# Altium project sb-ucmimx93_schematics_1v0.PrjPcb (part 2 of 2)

## Sheet 10 Console, RS232, SD, .SchDoc
size 420 x 297 mm; DocumentNumber: 10; SheetNumber: 10; SheetTotal: 12
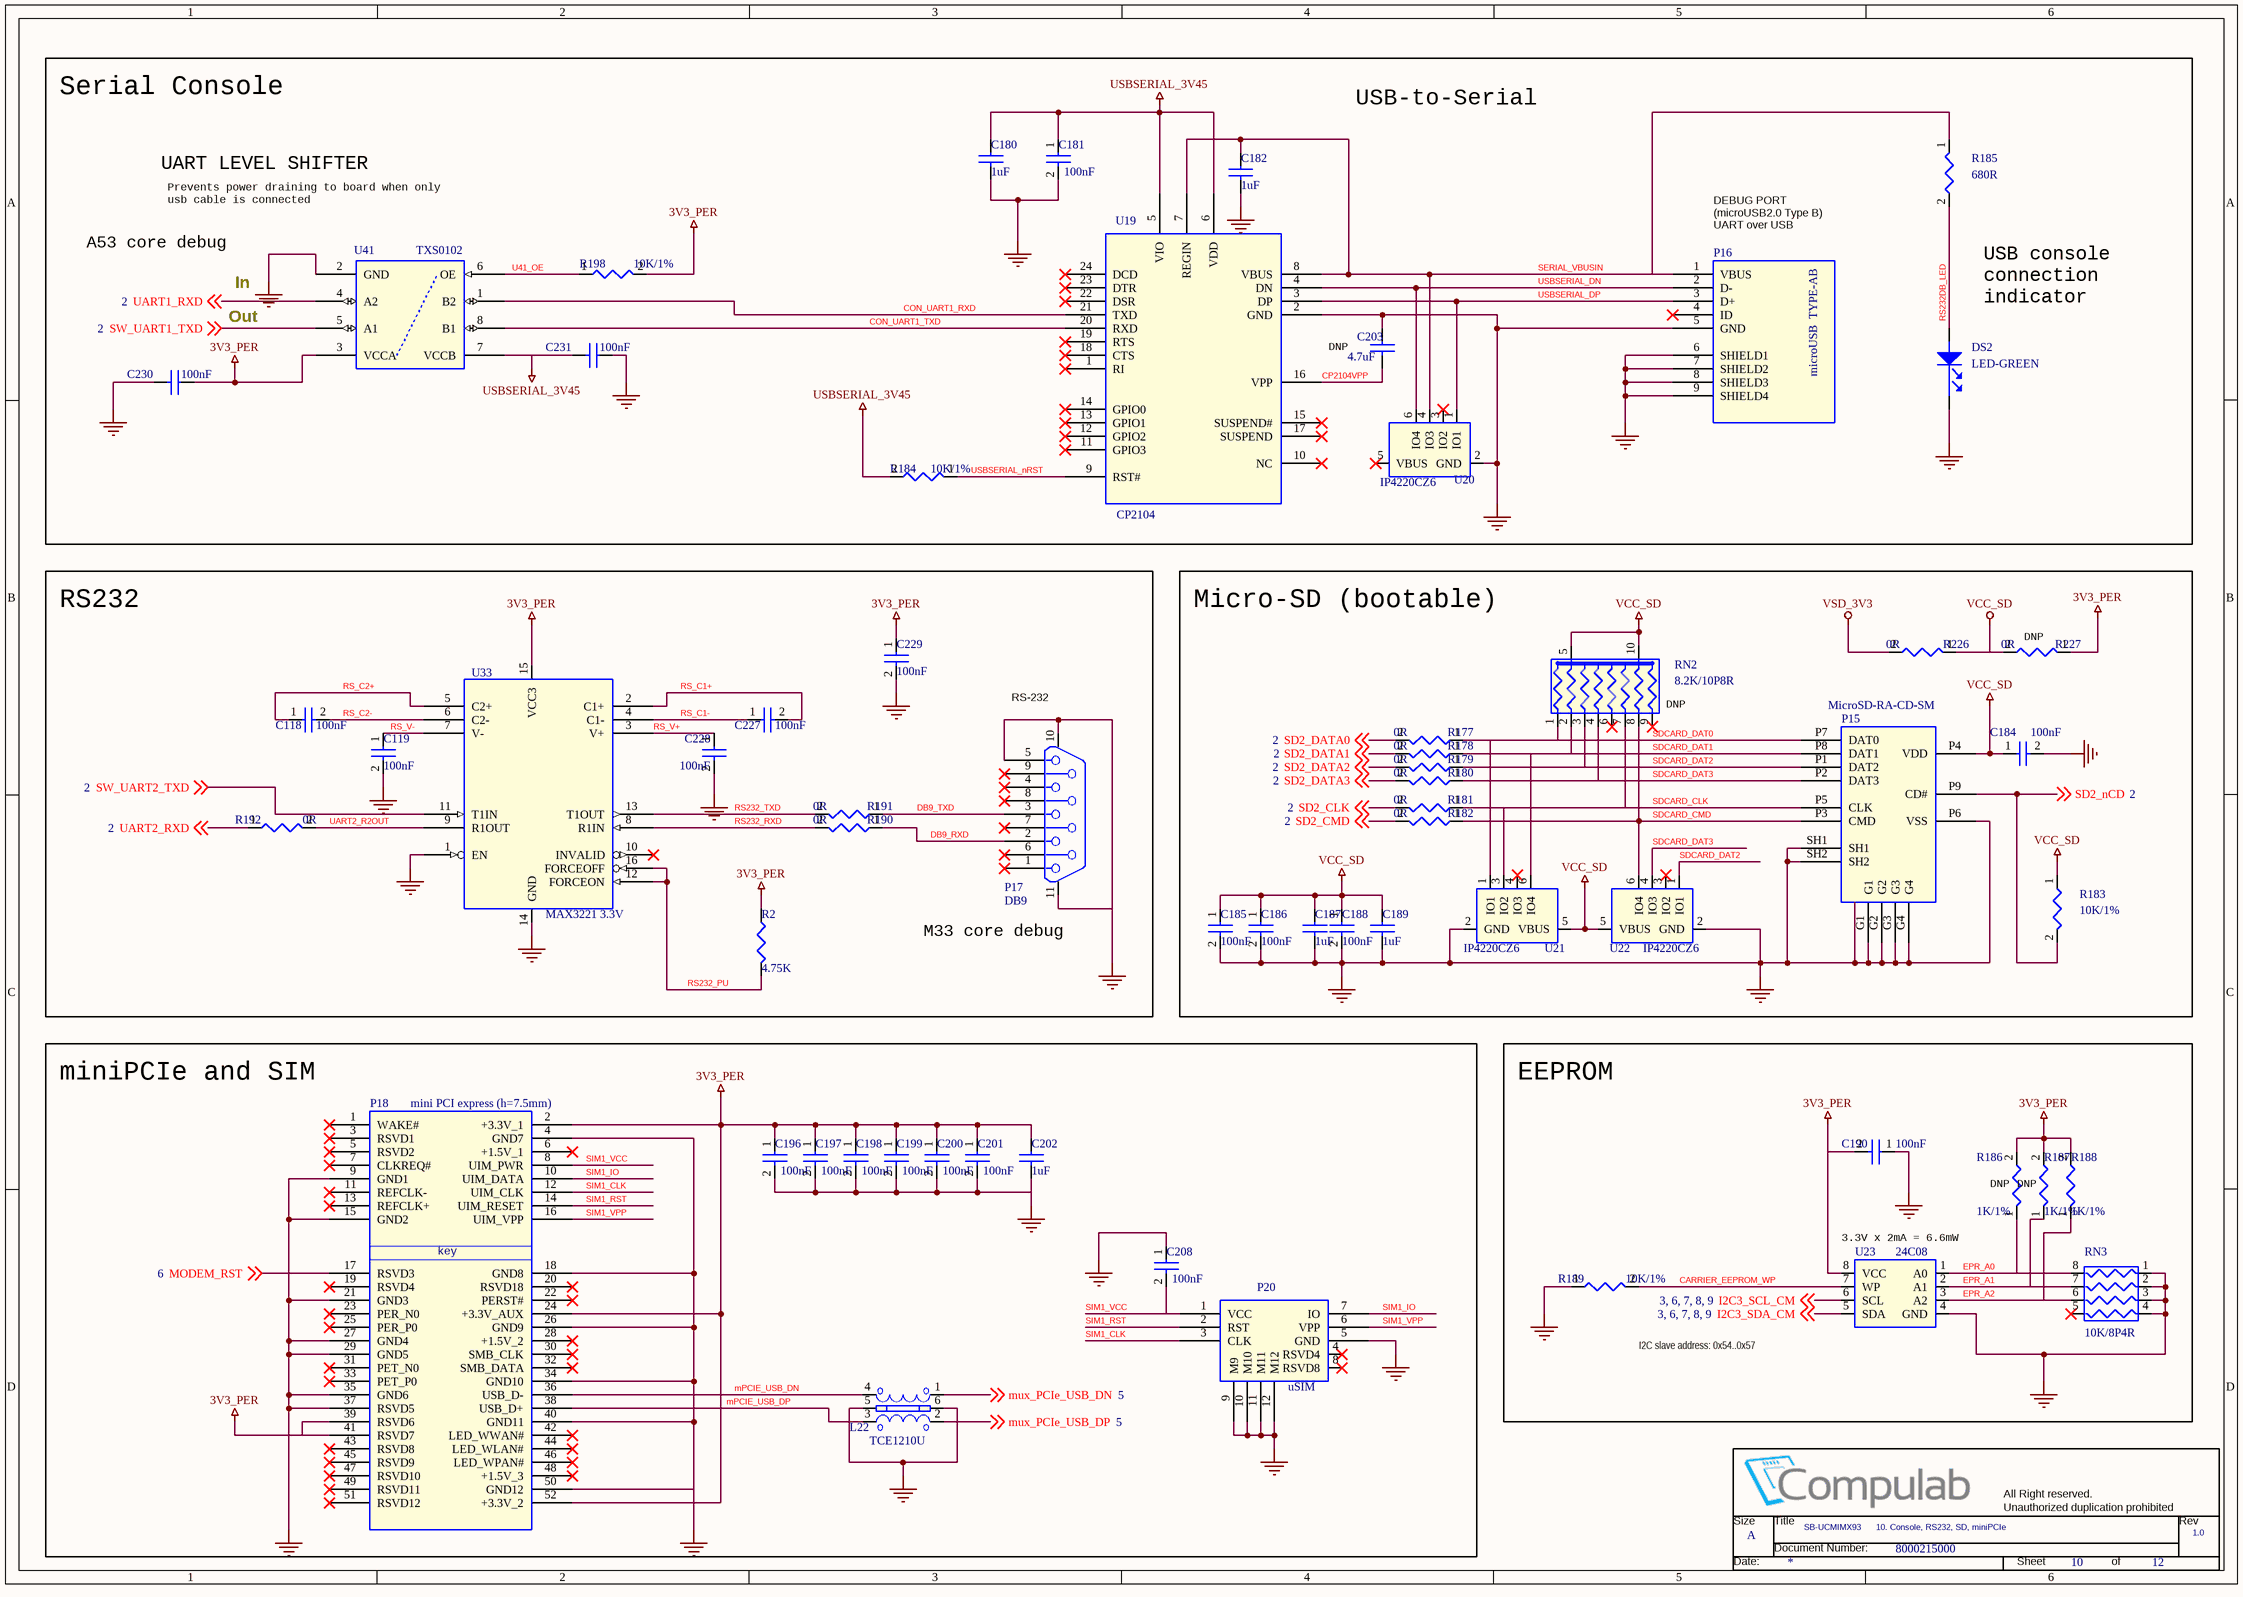
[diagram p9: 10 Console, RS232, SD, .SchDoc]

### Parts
(Parts that share a designator on the sheet are numbered #1, #2 ... from top to bottom, then left to right.)
*#11  Title: SB-UCMIMX93      10. Console, RS232, SD, miniPCIe  Doc: 8000215000  RevCode: 1.0  Page Size: A  Page Number: 10  Page Count: 12  (hidden comment: CompuLabTitleBlk)  (graphical)
C118  100nF  [RC0402]
C119  100nF  [RC0402]
C180  1uF  [RC0402]
C181  100nF  [RC0402]
C182  1uF  [RC0402]
C184  100nF  [RC0402]
C185  100nF  [RC0402]
C186  100nF  [RC0402]
C187  1uF  [RC0402]
C188  100nF  [RC0402]
C189  1uF  [RC0402]
C190  100nF  [RC0402]
C196  100nF  [RC0402]
C197  100nF  [RC0402]
C198  100nF  [RC0402]
C199  100nF  [RC0402]
C200  100nF  [RC0402]
C201  100nF  [RC0402]
C202  1uF  [RC0402]
C203  4.7uF  [C0603-08]
C208  100nF  [RC0402]
C227  100nF  [RC0402]
C228  100nF  [RC0402]
C229  100nF  [RC0402]
C230  100nF  [RC0402]
C231  100nF  [RC0402]
DS2  LED-GREEN  [LED-1206]
L22  TCE1210U  [EMI1012-ESD]
P15  MicroSD-RA-CD-SM  [MicroSD-RA-CD-SM]
P16  microUSB  TYPE-AB  [MICRO-USB-AB-RA-SM]
P17  DB9  [DB9RATH]
P18  mini PCI express (h=7.5mm)  [MINIPCIE-4]
P20  uSIM  [SKT-MicroSIM6-SM]
R2  4.75K  [RC0402]
R177  0R  [RC0402]
R178  0R  [RC0402]
R179  0R  [RC0402]
R180  0R  [RC0402]
R181  0R  [RC0402]
R182  0R  [RC0402]
R183  10K/1%  [RC0402]
R184  10K/1%  [RC0402]
R185  680R  [RC0402]
R186  1K/1%  [RC0402]
R187  1K/1%  [RC0402]
R188  1K/1%  [RC0402]
R189  10K/1%  [RC0402]
R190  0R  [RC0402]
R191  0R  [RC0402]
R192  0R  [RC0402]
R198  10K/1%  [RC0402]
R226  0R  [RC0402]
R227  0R  [RC0402]
RN2  8.2K/10P8R  [RESNET10P1206]
RN3  10K/8P4R  [RESNET8P0805]
U19  CP2104  [MO-220VGGD-8]
U20  IP4220CZ6  [SOT23-6L-H1]
U21  IP4220CZ6  [SOT23-6L]
U22  IP4220CZ6  [SOT23-6L]
U23  24C08  [MO-229VCED-2]
U33  MAX3221 3.3V  [SSOP-16]
U41  TXS0102  [MO-187DA-8]

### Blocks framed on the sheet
Serial Console: C180-C182 C203 C230 C231 DS2 P16 R184 R185 R198 U19 U20 U41
RS232: C118 C119 C227-C229 P17 R2 R190-R192 U33
Micro-SD (bootable): C184-C189 P15 R177-R183 R226 R227 RN2 U21 U22
miniPCIe and SIM: C196-C202 C208 L22 P18 P20
EEPROM: C190 R186-R189 RN3 U23

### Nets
3V3_PER: C190.2 C196.1 C197.1 C198.1 C199.1 C200.1 C201.1 C202.1 C229.1 C230.1 P18.2(+3.3V_1) P18.24(+3.3V_AUX) P18.39(RSVD6) P18.41(RSVD7) P18.52(+3.3V_2) R2.1 R186.2 R187.2 R188.2 R198.2 R227.1 U23.8(VCC) U33.15(VCC3) U41.3(VCCA)
GND: C119.2 C180.2 C181.2 C182.2 C184.2 C185.2 C186.2 C187.2 C188.2 C189.2 C190.1 C196.2 C197.2 C198.2 C199.2 C200.2 C201.2 C202.2 C203.2 C208.1 C228.2 C229.2 C230.2 C231.1 DS2.CATHODE L22.5(GND) L22.6(GND) P15.G1 P15.G2 P15.G3 P15.G4 P15.P6(VSS) P15.SH1 P15.SH2 P16.5(GND) P16.6(SHIELD1) P16.7(SHIELD2) P16.8(SHIELD3) P16.9(SHIELD4) P17.5 P17.10(BRACKET) P17.11(BRACKET) P18.4(GND7) P18.9(GND1) P18.15(GND2) P18.18(GND8) P18.21(GND3) P18.26(GND9) P18.27(GND4) P18.29(GND5) P18.34(GND10) P18.35(GND6) P18.37(RSVD5) P18.40(GND11) P18.50(GND12) P20.5(GND) P20.9(M9) P20.10(M10) P20.11(M11) P20.12(M12) R189.1 RN3.1(RA1) RN3.2(RB1) RN3.3(RC1) RN3.4(RD1) U19.2(GND) U20.2(GND) U21.2(GND) U22.2(GND) U23.4(GND) U33.1(EN) U33.14(GND) U41.2(GND)
USBSERIAL_3V45: C180.1 C181.1 C231.2 R184.2 U19.5(VIO) U19.6(VDD) U41.7(VCCB)
VCC_SD: C184.1 C185.1 C186.1 C187.1 C188.1 C189.1 P15.P4(VDD) R183.1 R226.1 R227.2 RN2.5(COM1) RN2.10(COM2) U21.5(VBUS) U22.5(VBUS)
VSD_3V3: R226.2
CARRIER_EEPROM_WP: R189.2 U23.7(WP)
CON_UART1_RXD: U19.21(TXD) U41.1(B2)
CON_UART1_TXD: U19.20(RXD) U41.8(B1)
CP2104VPP: C203.1 U19.16(VPP)
DB9_RXD: P17.2 R190.1
DB9_TXD: P17.3 R191.1
EPR_A0: R186.1 RN3.8(RA2) U23.1(A0)
EPR_A1: R187.1 RN3.7(RB2) U23.2(A1)
EPR_A2: R188.1 RN3.6(RC2) U23.3(A2)
I2C3_SCL_CM: U23.6(SCL) ; off-sheet I2C3_SCL_CM
I2C3_SDA_CM: U23.5(SDA) ; off-sheet I2C3_SDA_CM
MODEM_RST: P18.17(RSVD3) ; off-sheet MODEM_RST
mPCIE_USB_DN: L22.4 P18.36(USB_D-)
mPCIE_USB_DP: L22.3 P18.38(USB_D+)
mux_PCIe_USB_DN: L22.1 ; off-sheet mux_PCIe_USB_DN
mux_PCIe_USB_DP: L22.2 ; off-sheet mux_PCIe_USB_DP
RS232_PU: R2.2 U33.12(FORCEON) U33.16(FORCEOFF)
RS232_RXD: R190.2 U33.8(R1IN)
RS232_TXD: R191.2 U33.13(T1OUT)
RS232DB_LED: DS2.ANODE R185.2
RS_C1+: C227.2 U33.2(C1+)
RS_C1-: C227.1 U33.4(C1-)
RS_C2+: C118.1 U33.5(C2+)
RS_C2-: C118.2 U33.6(C2-)
RS_V+: C228.1 U33.3(V+)
RS_V-: C119.1 U33.7(V-)
SD2_CLK: R181.2 ; off-sheet SD2_CLK
SD2_CMD: R182.2 ; off-sheet SD2_CMD
SD2_DATA0: R177.2 ; off-sheet SD2_DATA0
SD2_DATA1: R178.2 ; off-sheet SD2_DATA1
SD2_DATA2: R179.2 ; off-sheet SD2_DATA2
SD2_DATA3: R180.2 ; off-sheet SD2_DATA3
SD2_nCD: P15.P9(CD#) R183.2 ; off-sheet SD2_nCD
SDCARD_CLK: P15.P5(CLK) R181.1 RN2.7(R6) U21.3(IO2)
SDCARD_CMD: P15.P3(CMD) R182.1 RN2.8(R7) U22.6(IO4)
SDCARD_DAT0: P15.P7(DAT0) R177.1 RN2.1(R1) U21.1(IO1)
SDCARD_DAT1: P15.P8(DAT1) R178.1 RN2.2(R2) U21.6(IO4)
SDCARD_DAT2: P15.P1(DAT2) R179.1 RN2.3(R3) U22.1(IO1)
SDCARD_DAT3: P15.P2(DAT3) R180.1 RN2.4(R4) U22.4(IO3)
SERIAL_VBUSIN: C182.1 P16.1(VBUS) R185.1 U19.7(REGIN) U19.8(VBUS) U20.4(IO3)
SIM1_CLK: P18.12(UIM_CLK) P20.3(CLK)
SIM1_IO: P18.10(UIM_DATA) P20.7(IO)
SIM1_RST: P18.14(UIM_RESET) P20.2(RST)
SIM1_VCC: C208.2 P18.8(UIM_PWR) P20.1(VCC)
SIM1_VPP: P18.16(UIM_VPP) P20.6(VPP)
SW_UART1_TXD: U41.5(A1) ; off-sheet SW_UART1_TXD
SW_UART2_TXD: U33.11(T1IN) ; off-sheet SW_UART2_TXD
U41_OE: R198.1 U41.6(OE)
UART1_RXD: U41.4(A2) ; off-sheet UART1_RXD
UART2_R2OUT: R192.2 U33.9(R1OUT)
UART2_RXD: R192.1 ; off-sheet UART2_RXD
USBSERIAL_DN: P16.2(D-) U19.4(DN) U20.6(IO4)
USBSERIAL_DP: P16.3(D+) U19.3(DP) U20.1(IO1)
USBSERIAL_nRST: R184.1 U19.9(RST#)

Not connected (* = marked no-connect by the designer): P16 4(ID)*; P17 1* 4* 6* 7* 8* 9*; P18 1(WAKE#)* 3(RSVD1)* 5(RSVD2)* 6(+1.5V_1)* 7(CLKREQ#)* 11(REFCLK-)* 13(REFCLK+)* 19(RSVD4)* 20(RSVD18)* 22(PERST#)* 23(PER_N0)* 25(PER_P0)* 28(+1.5V_2)* 30(SMB_CLK)* 31(PET_N0)* 32(SMB_DATA)* 33(PET_P0)* 42(LED_WWAN#)* 43(RSVD8)* 44(LED_WLAN#)* 45(RSVD9)* 46(LED_WPAN#)* 47(RSVD10)* 48(+1.5V_3)* 49(RSVD11)* 51(RSVD12)*; P20 4(RSVD4)* 8(RSVD8)*; RN2 6(R5)* 9(R8)*; RN3 5(RD2)*; U19 1(RI)* 10(NC)* 11(GPIO3)* 12(GPIO2)* 13(GPIO1)* 14(GPIO0)* 15(SUSPEND#)* 17(SUSPEND)* 18(CTS)* 19(RTS)* 22(DSR)* 23(DTR)* 24(DCD)*; U20 3(IO2)* 5(VBUS)*; U21 4(IO3)*; U22 3(IO2)*; U33 10(INVALID)*

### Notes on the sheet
- USB-to-Serial
- UART LEVEL SHIFTER
- A53 core debug
- Prevents power draining to board when only
  usb cable is connected
- (near P16) DEBUG PORT
  (microUSB2.0 Type B)
  UART over USB
- Out
- In
- USB console
  connection
  indicator
- DNP
- (near R227) DNP
- (near P17) RS-232
- (near RN2) DNP
- (near P17) M33 core debug
- (near R186) DNP
- (near U23) 3.3V x 2mA = 6.6mW
- I2C slave address: 0x54..0x57

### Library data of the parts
C118 C119 C181 C184-C186 C188 C190 C196-C201 C208 C227-C229 = 100nF, 10V, X7R, 10%, 0402_Dup1: P/N: 151B10400S
C180 C182 C187 C189 C202 = 1uF,X5R,6.3V,0402: P/N: 151B10500S
C203 = 4.7uF, 6.3V, X5R, 20%, 0603: P/N: 151B10610S; CLABCONF0: DNP
C230 C231 = 100nF, 10V, X7R, 10%, 0402_0: P/N: 151B10400S
DS2 = LED-GREEN 1206_2: P/N: 139A10020S
L22 = ESD_CHOKE_DIFFx2_10: P/N: 142D11801S
P15 = microSD_push-pull: P/N: 182K01300S
P16 = Conn., Micro-USB, B-Type: P/N: 180K00501S
P17 = DB9 RA TH Male ATX: P/N: 180K00901
P18 = mini PCIe_0: P/N: 182K05202S
P20 = uSIM SOCKET_0: P/N: 190I00601S
R2 = 10K,1%,0402,1/16W_0: P/N: 161C47511S; Group: Always
R177-R182 R190 R191 = 0R, 0402_1: P/N: 161C00005S
R183 = 10K,1%,0402,1/16W_0_Dup1: P/N: 161C10021S
R184 R189 R198 = 10K,1%,0402,1/16W: P/N: 161C10021S
R185 = 47K, 0402: P/N: 161C68001S
R186 = 1K,1%,0402,1/16W: P/N: 161C10011S; Group: CAN; CLABCONF0: DNP
R187 = 1K,1%,0402,1/16W: P/N: 161C10011S; CLABCONF0: DNP; Group: CAN
R188 = 1K,1%,0402,1/16W: P/N: 161C10011S; Group: CAN
R192 = 0R, 0402: P/N: 161C00005S
R226 = 0R, 0402_0: P/N: 161C00005S
R227 = 0R, 0402_0: P/N: 161C00005S; CLABCONF0: DNP
RN2 = RN,8.2K,10P8R@1206: P/N: 163I08822S; CLABCONF0: DNP
RN3 = RN,10K,8P4R@0805: P/N: 163K04103S
U19 = CP2104_0: P/N: 116A00140S
U20-U22 = IP4220CZ6_0: P/N: 132D42200S
U23 = 24C02, serial EE, 2KB, I2C: P/N: 111S31000S
U33 = MAX3221 RS-232 1T1R 3_2.3V XCVR: P/N: 116A32210I
U41 = TXS0102_0: P/N: 116A01020S

## Sheet 11 Power.SchDoc
size 420 x 297 mm; DocumentNumber: 11; SheetNumber: 11; SheetTotal: 12
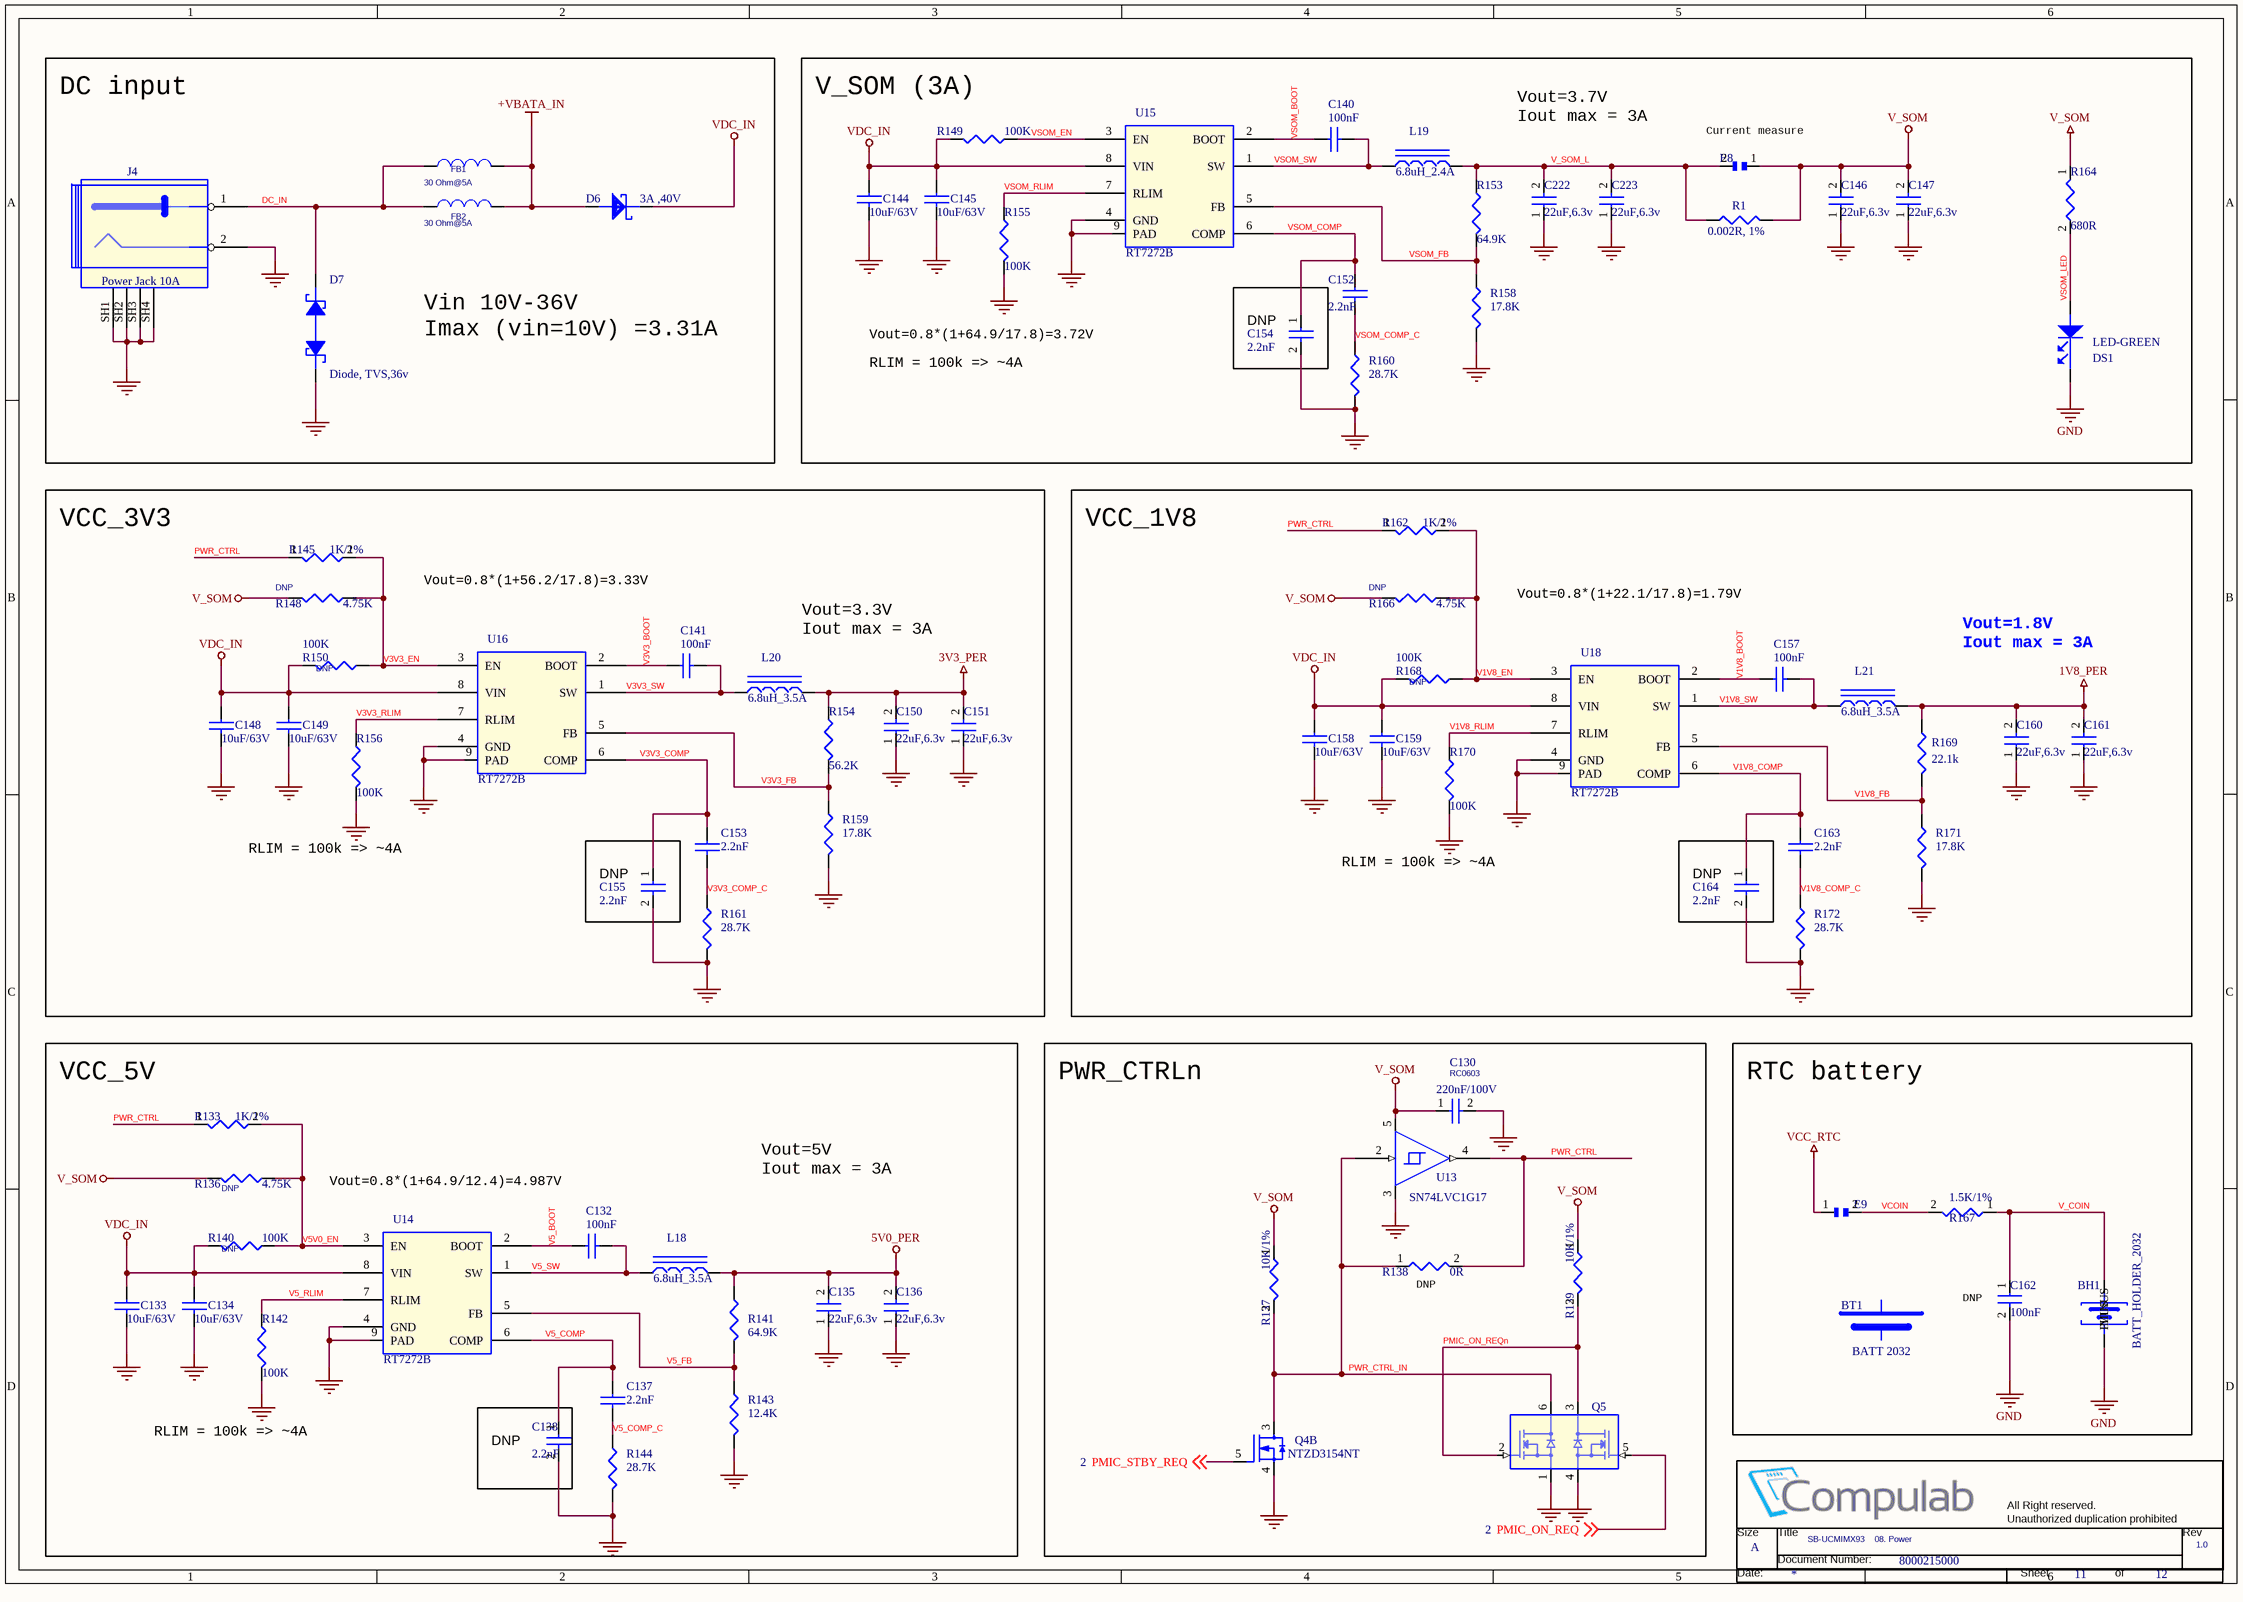
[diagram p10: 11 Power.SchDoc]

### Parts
(Parts that share a designator on the sheet are numbered #1, #2 ... from top to bottom, then left to right.)
*#12  Title: SB-UCMIMX93    08. Power  Doc: 8000215000  RevCode: 1.0  Page Size: A  Page Number: 11  Page Count: 12  (hidden comment: CompuLabTitleBlk)  (graphical)
BH1  BATT_HOLDER_2032  [BATTH20MM]
BT1  BATT 2032  [1X2THHDR]  (mechanical)
C130  220nF/100V  [RC0603]
C132  100nF  [RC0402]
C133  10uF/63V  [C1210H2_5]
C134  10uF/63V  [C1210H2_5]
C135  22uF,6.3v  [RC0603]
C136  22uF,6.3v  [RC0603]
C137  2.2nF  [RC0402]
C138  2.2nF  [RC0402]
C140  100nF  [RC0402]
C141  100nF  [RC0402]
C144  10uF/63V  [C1210H2_5]
C145  10uF/63V  [C1210H2_5]
C146  22uF,6.3v  [RC0603]
C147  22uF,6.3v  [RC0603]
C148  10uF/63V  [C1210H2_5]
C149  10uF/63V  [C1210H2_5]
C150  22uF,6.3v  [RC0603]
C151  22uF,6.3v  [RC0603]
C152  2.2nF  [RC0402]
C153  2.2nF  [RC0402]
C154  2.2nF  [RC0402]
C155  2.2nF  [RC0402]
C157  100nF  [RC0402]
C158  10uF/63V  [C1210H2_5]
C159  10uF/63V  [C1210H2_5]
C160  22uF,6.3v  [RC0603]
C161  22uF,6.3v  [RC0603]
C162  100nF  [RC0402]
C163  2.2nF  [RC0402]
C164  2.2nF  [RC0402]
C222  22uF,6.3v  [RC0603]
C223  22uF,6.3v  [RC0603]
D6  3A ,40V  [DO-214AC]
D7  Diode, TVS,36v  [SOD-323]
DS1  LED-GREEN  [LED-1206]
E8  HDR1X2  [1X2THHDR]  (value not drawn)
E9  HDR1X2  [1X2THHDR]  (value not drawn)
FB1  30 Ohm@5A  [FB0603]
FB2  30 Ohm@5A  [FB0603]
J4  Power Jack 10A  [PJ-0810-TH]
L18  6.8uH_3.5A  [IND6x5_5x3]
L19  6.8uH_2.4A  [IND6x5_5x3]
L20  6.8uH_3.5A  [IND6x5_5x3]
L21  6.8uH_3.5A  [IND6x5_5x3]
Q4  NTZD3154NT  [SOT-563-6]  (part B of 2)
Q5  0.5A,20V,Vgs max 6V  [SOT-563-6]  (value not drawn)
R1  0.002R, 1%  [R1206]
R133  1K/1%  [RC0402]
R136  4.75K  CLABCONF0: DNP  [RC0402]
R137  10K/1%  [RC0402]
R138  0R  [RC0402]
R139  10K/1%  [RC0402]
R140  100K  CLABCONF0: DNP  [RC0402]
R141  64.9K  [RC0402]
R142  100K  [RC0402]
R143  12.4K  [RC0402]
R144  28.7K  [RC0402]
R145  1K/1%  [RC0402]
R148  4.75K  CLABCONF0: DNP  [RC0402]
R149  100K  [RC0402]
R150  100K  CLABCONF0: DNP  [RC0402]
R153  64.9K  [RC0402]
R154  56.2K  [RC0402]
R155  100K  [RC0402]
R156  100K  [RC0402]
R158  17.8K  [RC0402]
R159  17.8K  [RC0402]
R160  28.7K  [RC0402]
R161  28.7K  [RC0402]
R162  1K/1%  [RC0402]
R164  680R  [RC0402]
R166  4.75K  CLABCONF0: DNP  [RC0402]
R167  1.5K/1%  [RC0402]
R168  100K  CLABCONF0: DNP  [RC0402]
R169  22.1k  [RC0402]
R170  100K  [RC0402]
R171  17.8K  [RC0402]
R172  28.7K  [RC0402]
U13  SN74LVC1G17  [SC70]
U14  RT7272B  [PSOP-8-2X2]
U15  RT7272B  [PSOP-8-2X2]
U16  RT7272B  [PSOP-8-2X2]
U18  RT7272B  [PSOP-8-2X2]

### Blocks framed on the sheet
DC input: D6 D7 FB1 FB2 J4
V_SOM (3A): C140 C144-C147 C152 C222 C223 DS1 E8 L19 R1 R149 R153 R155 R158 R160 R164 U15
DNP: C154
VCC_3V3: C141 C148-C151 C153 L20 R145 R148 R150 R154 R156 R159 R161 U16
VCC_1V8: C157-C161 C163 L21 R162 R166 R168-R172 U18
DNP: C155
DNP: C164
VCC_5V: C132-C137 L18 R133 R136 R140-R144 U14
PWR_CTRLn: C130 Q4 Q5 R137-R139 U13
RTC battery: BH1 BT1 C162 E9 R167
DNP: C138

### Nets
1V8_PER: C160.2 C161.2 L21.2 R169.1
3V3_PER: C150.2 C151.2 L20.2 R154.1
5V0_PER: C135.2 C136.2 L18.2 R141.1
+VBATA_IN: D6.ANODE FB1.2 FB2.2
GND: BH1.1(MINUS) C130.2 C133.2 C134.2 C135.1 C136.1 C138.2 C144.2 C145.2 C146.1 C147.1 C148.2 C149.2 C150.1 C151.1 C154.2 C155.2 C158.2 C159.2 C160.1 C161.1 C162.2 C164.2 C222.1 C223.1 D7.ANODE DS1.CATHODE J4.2(R) J4.SH1 J4.SH2 J4.SH3 J4.SH4 Q4.4(S) Q5.1(S1) Q5.4(S2) R142.2 R143.2 R144.2 R155.2 R156.2 R158.2 R159.2 R160.2 R161.2 R170.2 R171.2 R172.2 U13.3(GND) U14.4(GND) U14.9(PAD) U15.4(GND) U15.9(PAD) U16.4(GND) U16.9(PAD) U18.4(GND) U18.9(PAD)
V_SOM: C130.1 C146.2 C147.2 E8.1 R1.2 R136.2 R137.1 R139.1 R148.2 R164.1 R166.2 U13.5(VCC)
VCC_RTC: E9.1
VDC_IN: C133.1 C134.1 C144.1 C145.1 C148.1 C149.1 C158.1 C159.1 D6.CATHODE R140.2 R149.2 R150.2 R168.2 U14.8(VIN) U15.8(VIN) U16.8(VIN) U18.8(VIN)
DC_IN: D7.CATHODE FB1.1 FB2.1 J4.1(CENTRAL)
PMIC_ON_REQ: Q5.5(G2) ; off-sheet PMIC_ON_REQ
PMIC_ON_REQn: Q5.2(G1) Q5.3(D2) R139.2
PMIC_STBY_REQ: Q4.5(G) ; off-sheet PMIC_STBY_REQ
PWR_CTRL: R133.1 R138.2 R145.1 R162.1 U13.4(Y)
PWR_CTRL_IN: Q4.3(D) Q5.6(D1) R137.2 R138.1 U13.2(A)
V1V8_BOOT: C157.1 U18.2(BOOT)
V1V8_COMP: C163.1 C164.1 U18.6(COMP)
V1V8_COMP_C: C163.2 R172.1
V1V8_EN: R162.2 R166.1 R168.1 U18.3(EN)
V1V8_FB: R169.2 R171.1 U18.5(FB)
V1V8_RLIM: R170.1 U18.7(RLIM)
V1V8_SW: C157.2 L21.1 U18.1(SW)
V3V3_BOOT: C141.1 U16.2(BOOT)
V3V3_COMP: C153.1 C155.1 U16.6(COMP)
V3V3_COMP_C: C153.2 R161.1
V3V3_EN: R145.2 R148.1 R150.1 U16.3(EN)
V3V3_FB: R154.2 R159.1 U16.5(FB)
V3V3_RLIM: R156.1 U16.7(RLIM)
V3V3_SW: C141.2 L20.1 U16.1(SW)
V5_BOOT: C132.1 U14.2(BOOT)
V5_COMP: C137.1 C138.1 U14.6(COMP)
V5_COMP_C: C137.2 R144.1
V5_FB: R141.2 R143.1 U14.5(FB)
V5_RLIM: R142.1 U14.7(RLIM)
V5_SW: C132.2 L18.1 U14.1(SW)
V5V0_EN: R133.2 R136.1 R140.1 U14.3(EN)
V_COIN: BH1.2(PLUS) C162.1 R167.1
V_SOM_L: C222.2 C223.2 E8.2 L19.2 R1.1 R153.1
VCOIN: E9.2 R167.2
VSOM_BOOT: C140.1 U15.2(BOOT)
VSOM_COMP: C152.1 C154.1 U15.6(COMP)
VSOM_COMP_C: C152.2 R160.1
VSOM_EN: R149.1 U15.3(EN)
VSOM_FB: R153.2 R158.1 U15.5(FB)
VSOM_LED: DS1.ANODE R164.2
VSOM_RLIM: R155.1 U15.7(RLIM)
VSOM_SW: C140.2 L19.1 U15.1(SW)

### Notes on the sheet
- Vout=3.7V
  Iout max = 3A
- (near E8) Current measure
- Vin 10V-36V
  Imax (vin=10V) =3.31A
- Vout=0.8*(1+64.9/17.8)=3.72V
- RLIM = 100k => ~4A
- Vout=0.8*(1+56.2/17.8)=3.33V
- Vout=3.3V
  Iout max = 3A
- Vout=0.8*(1+22.1/17.8)=1.79V
- Vout=1.8V
  Iout max = 3A
- Vout=0.8*(1+64.9/12.4)=4.987V
- Vout=5V
  Iout max = 3A
- (near R138) DNP
- (near C162) DNP

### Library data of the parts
BH1 = BATT_HOLDER_0: P/N: 190Z00201
BT1 = BATT 2032: P/N: 210C30002
C130 = 100nF, 10V, X7R, 10%, 0402_Dup1: P/N: 151E22410S
C132 C140 C141 C157 = 100nF, 10V, X7R, 10%, 0402_0: P/N: 151B10400S; Group: LAN2
C133 C134 C148 C149 C158 C159 = 22uF/25V: P/N: 151E10680S
C135 C136 C146 C147 C150 C151 C160 C161 C222 C223 = 100nF, 10V, X7R, 10%, 0402: P/N: 151B22610S
C137 C152 C153 C163 = 2.2nF, 50V, X7R, 10%, 0402: P/N: 151D22200S
C138 C154 C155 C164 = 2.2nF, 50V, X7R, 10%, 0402_Dup1: P/N: 151D22200S; CLABCONF0: DNP
C144 C145 = 22uF/25V: P/N: 151D10630S
C162 = 100nF, 10V, X7R, 10%, 0402_Dup1: P/N: 151B10400S; CLABCONF0: DNP
D6 = Diode Shotky,5A,30V_0: P/N: 130E40001S
D7 = 1A Schottky Barrier Rectifier_1: P/N: 132D10080S
DS1 = LED-GREEN 1206_2: P/N: 139A10020S
E8 E9 = HDR 1x2 100MIL TH JUMPER: P/N: 190C00200
FB1 FB2 = Ferrite bead , 30 Ohm@5A: P/N: 147D30000S
J4 = DC Jack ,5.5/2.5,10A,20V: P/N: 180K00200
L18 L20 L21 = IND 6.8uH 3.5A: P/N: 147A6R802S
L19 = IND 6.8uH 3.5A: P/N: 147A6R804S
Q4 = N-MOSFET_Dual: P/N: 131D31540S
Q5 = DUAL N-MOSFET, 0.5A 20V: P/N: 131D31540S
R1 = RESISTOR: P/N: 161F00211S
R133 R145 R162 = 1K,1%,0402,1/16W: P/N: 161C10011S; Group: CAN
R136 R148 R166 = 100K, 0402_0: P/N: 161C47511S
R137 R139 = 10K,1%,0402,1/16W: P/N: 161C10021S
R138 = 0R, 0402: P/N: 161C00005S; CLABCONF0: DNP
R140 R142 R149 R150 R155 R156 R168 R170 = 100K, 0402_0: P/N: 161C10035S
R141 R153 = 10.5K/1%,0402: P/N: 161C64921S
R143 = 2.37K/1%, 0402: P/N: 161C12421S
R144 R160 R161 R172 = 40.2k/1%: P/N: 161C28721S
R154 = 10.5K/1%,0402: P/N: 161C56221S
R158 R159 R171 = 2.37K/1%, 0402: P/N: 161C17821S
R164 = 47K, 0402: P/N: 161C68001S
R167 = 1.5K/1%, 0402: P/N: 161C15011S
R169 = RESISTOR: P/N: 161C22121S
U13 = SN74LVC1G17: P/N: 106D90000S
U14-U16 U18 = RT7272B,Converter,3A,36V: P/N: 123V30000S

## Sheet 12 Mechanical.SchDoc
size 420 x 297 mm; DocumentNumber: 12; SheetNumber: 12; SheetTotal: 12
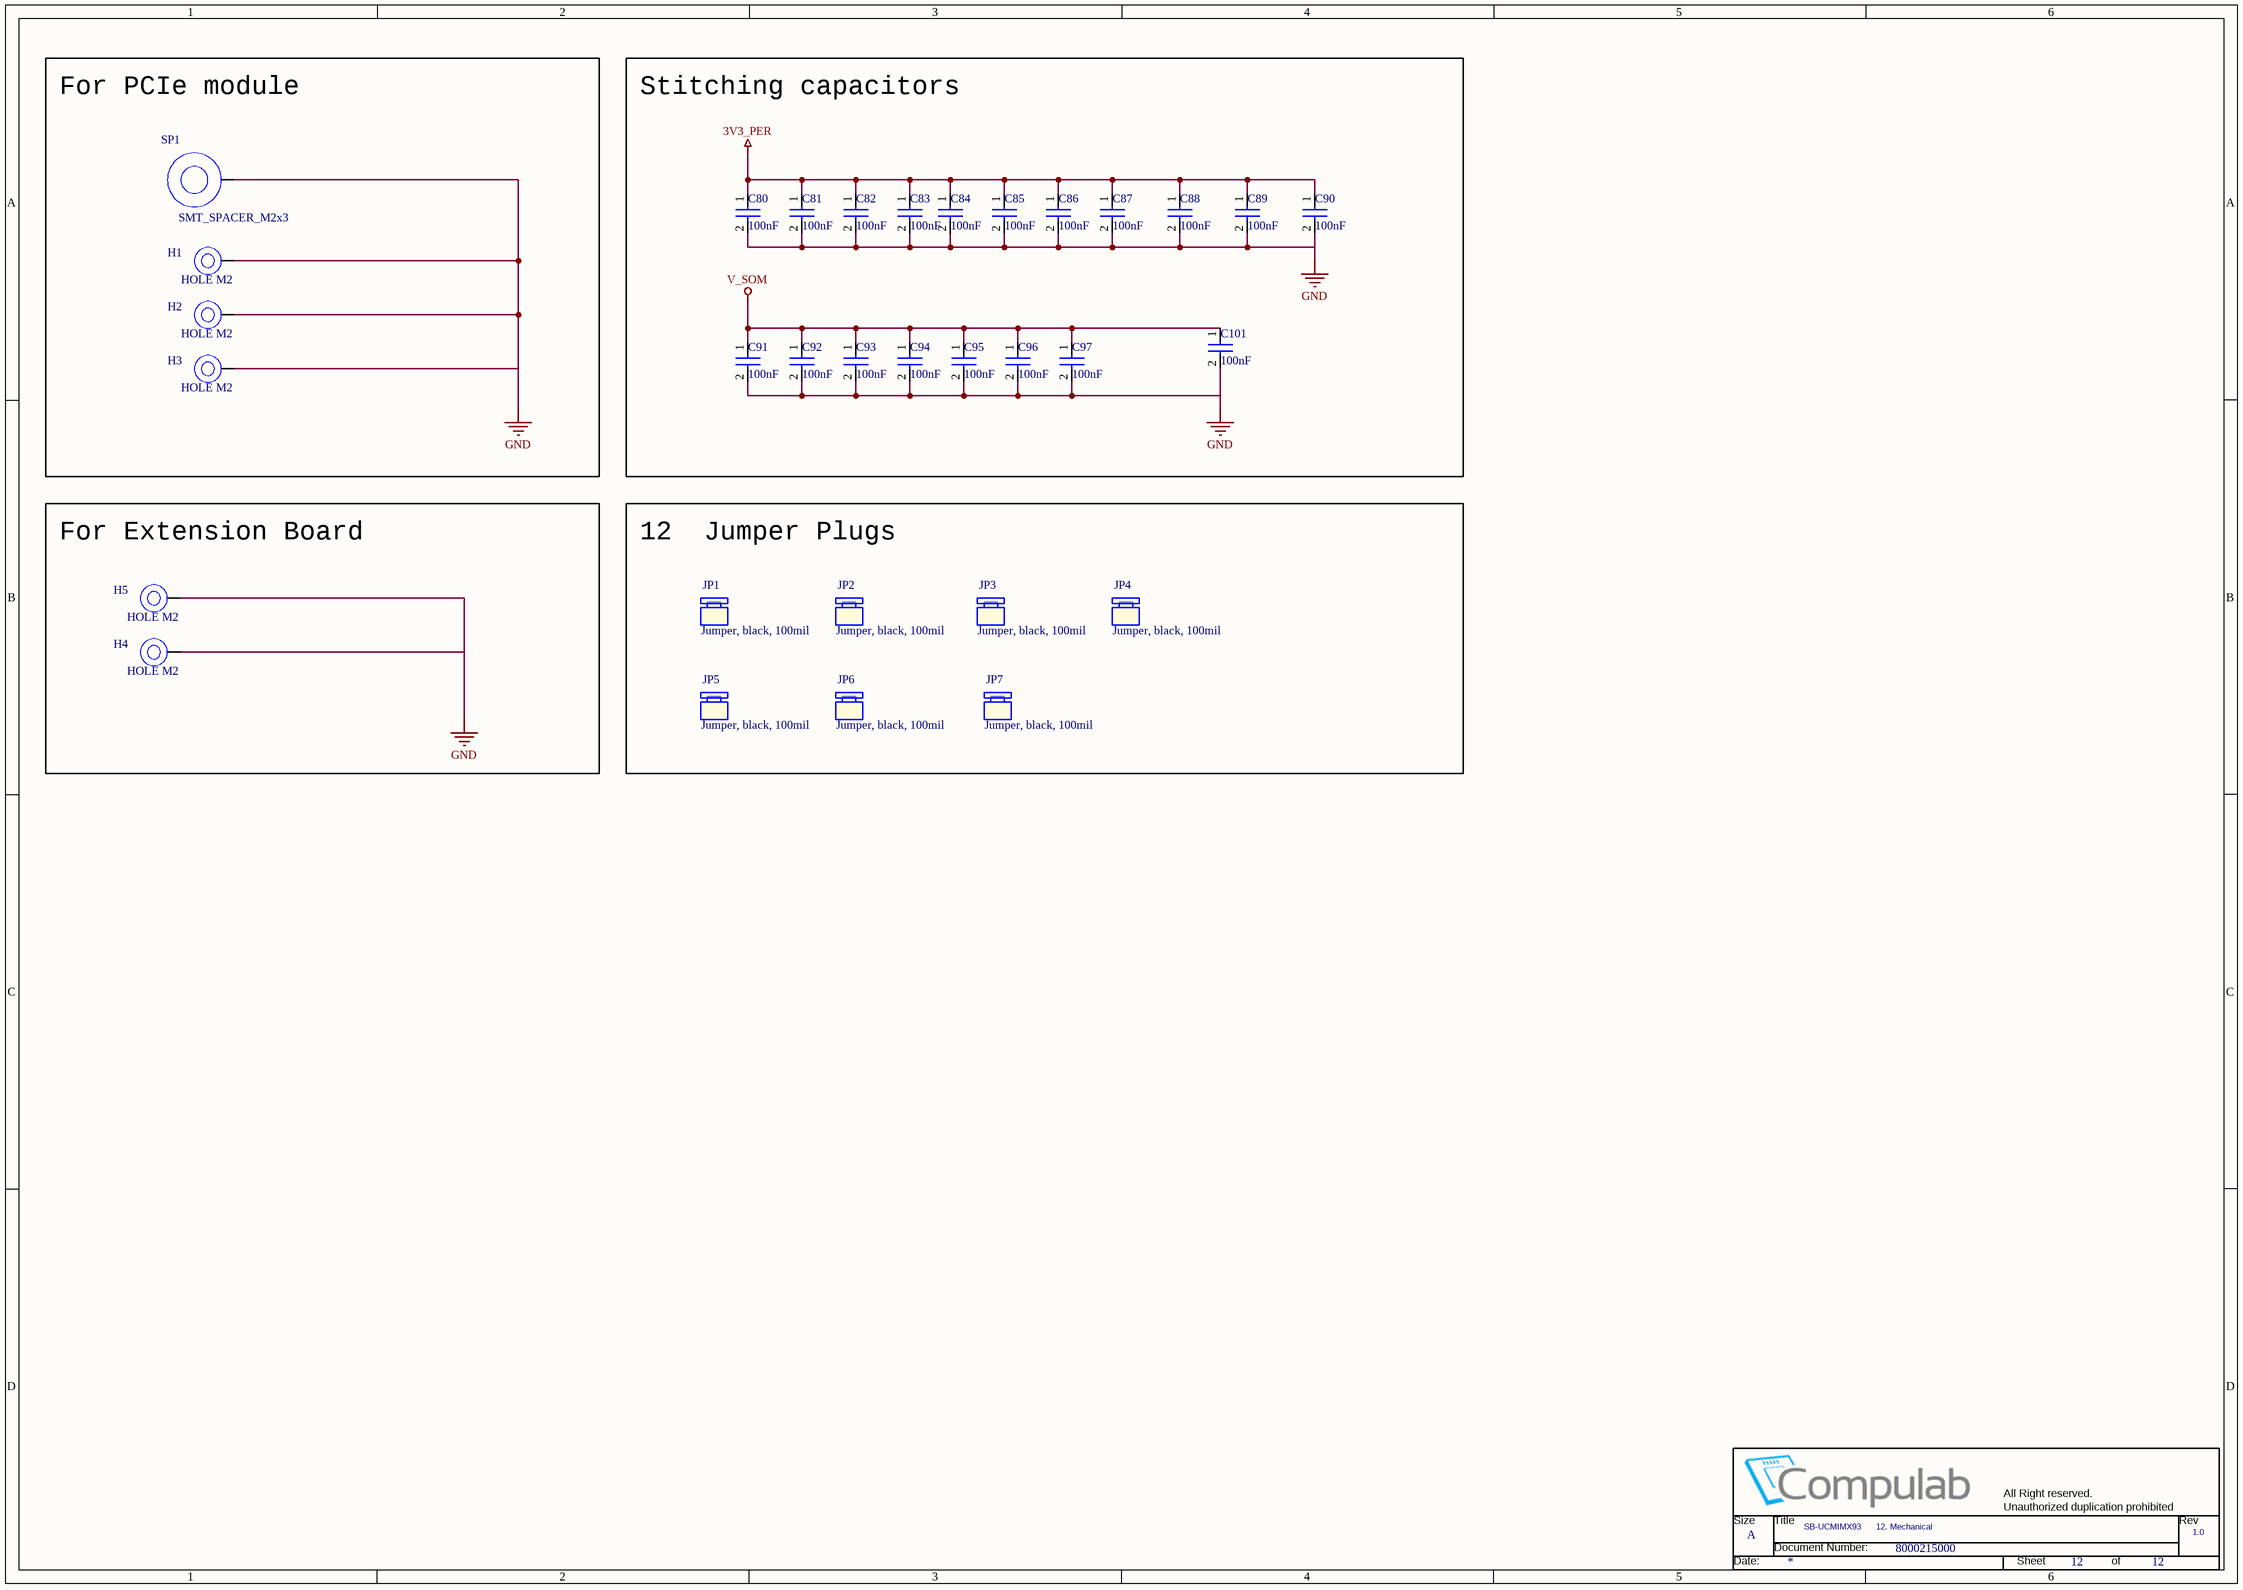
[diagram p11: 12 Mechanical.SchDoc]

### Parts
(Parts that share a designator on the sheet are numbered #1, #2 ... from top to bottom, then left to right.)
*#13  Title: SB-UCMIMX93      12. Mechanical  Doc: 8000215000  RevCode: 1.0  Page Size: A  Page Number: 12  (hidden comment: CompuLabTitleBlk)  (graphical)
C80  100nF  [RC0402]
C81  100nF  [RC0402]
C82  100nF  [RC0402]
C83  100nF  [RC0402]
C84  100nF  [RC0402]
C85  100nF  [RC0402]
C86  100nF  [RC0402]
C87  100nF  [RC0402]
C88  100nF  [RC0402]
C89  100nF  [RC0402]
C90  100nF  [RC0402]
C91  100nF  [RC0402]
C92  100nF  [RC0402]
C93  100nF  [RC0402]
C94  100nF  [RC0402]
C95  100nF  [RC0402]
C96  100nF  [RC0402]
C97  100nF  [RC0402]
C101  100nF  [RC0402]
H1  HOLE M2  [M2PAD]
H2  HOLE M2  [M2PAD]
H3  HOLE M2  [M2PAD]
H4  HOLE M2  [M2PAD]
H5  HOLE M2  [M2PAD]
JP1  Jumper, black, 100mil  [1X2THHDR]  (mechanical)
JP2  Jumper, black, 100mil  [2X5SMHDR]  (mechanical)
JP3  Jumper, black, 100mil  [2X5SMHDR]  (mechanical)
JP4  Jumper, black, 100mil  [2X17SMHDR]  (mechanical)
JP5  Jumper, black, 100mil  [21-0181B_T423590M-1_MXM]  (mechanical)
JP6  Jumper, black, 100mil  [0402]  (mechanical)
JP7  Jumper, black, 100mil  [0402]  (mechanical)
SP1  SMT_SPACER_M2x3  [MINIPCIE-4-Spacer]

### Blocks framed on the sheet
For PCIe module: H1-H3 SP1
Stitching capacitors: C80-C97 C101
For Extension Board: H4 H5
12  Jumper Plugs: JP1-JP7

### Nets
3V3_PER: C80.1 C81.1 C82.1 C83.1 C84.1 C85.1 C86.1 C87.1 C88.1 C89.1 C90.1
GND: C80.2 C81.2 C82.2 C83.2 C84.2 C85.2 C86.2 C87.2 C88.2 C89.2 C90.2 C91.2 C92.2 C93.2 C94.2 C95.2 C96.2 C97.2 C101.2 H1.1 H2.1 H3.1 H4.1 H5.1 SP1.NC
V_SOM: C91.1 C92.1 C93.1 C94.1 C95.1 C96.1 C97.1 C101.1

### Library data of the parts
C80-C97 C101 = 100nF, 10V, X7R, 10%, 0402_Dup1: P/N: 151B10400S
H1-H5 = Hole, Plated, M2, 5mm. ext.: P/N: 188Z10010; CLABCONF0: DNP
JP1-JP7 = Jumper, black, 100mil: P/N: 185B10010
SP1 = SMT_SPACER_M2x3_1: P/N: 383B52520S

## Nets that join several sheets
1V8_PER: 03 Ethernet and Expansi (7 pins), 05 USB2, JTAG, SPDIF (R42.1), 09 MIPI-CSI Camera Conn (C114.1 C115.1 P10.3 R122.1), 11 Power (C160.2 C161.2 L21.2 R169.1)
3V3_PER: 02 SOM Connectors (6 pins), 03 Ethernet and Expansi (11 pins), 04 USB1 (C212.2 R210.2 R215.2 U27.9), 05 USB2, JTAG, SPDIF (6 pins), 06 CAN, RS485, GPIO, MI (14 pins), 07 MIPI-DSI LCD (7 pins), 08 LVDS LCD (13 pins), 09 MIPI-CSI Camera Conn (23 pins), 10 Console, RS232, SD,  (24 pins), 11 Power (C150.2 C151.2 L20.2 R154.1), 12 Mechanical (11 pins)
5V0_PER: 03 Ethernet and Expansi (C183.1 P14.44), 04 USB1 (7 pins), 05 USB2, JTAG, SPDIF (C219.2 U31.6 U31.7), 06 CAN, RS485, GPIO, MI (9 pins), 08 LVDS LCD (R86.1), 11 Power (C135.2 C136.2 L18.2 R141.1)
GND: 02 SOM Connectors (41 pins), 03 Ethernet and Expansi (33 pins), 04 USB1 (32 pins), 05 USB2, JTAG, SPDIF (25 pins), 06 CAN, RS485, GPIO, MI (26 pins), 07 MIPI-DSI LCD (39 pins), 08 LVDS LCD (38 pins), 09 MIPI-CSI Camera Conn (61 pins), 10 Console, RS232, SD,  (73 pins), 11 Power (56 pins), 12 Mechanical (25 pins)
V_SOM: 02 SOM Connectors (32 pins), 11 Power (12 pins), 12 Mechanical (8 pins)
VCC_RTC: 02 SOM Connectors (P1.93), 11 Power (E9.1)
VDC_IN: 03 Ethernet and Expansi (D9.CATHODE), 11 Power (17 pins)
VSD_3V3: 02 SOM Connectors (P1.17), 10 Console, RS232, SD,  (R226.2)
ADC_IN0: 02 SOM Connectors (P2.89), 06 CAN, RS485, GPIO, MI (P3.9)
ADC_IN1: 02 SOM Connectors (P2.91), 06 CAN, RS485, GPIO, MI (P3.11)
ADC_IN2: 02 SOM Connectors (P2.93), 06 CAN, RS485, GPIO, MI (P3.13)
ADC_IN3: 02 SOM Connectors (P2.95), 06 CAN, RS485, GPIO, MI (P3.15)
AUD_nINT: 03 Ethernet and Expansi (P14.8), 06 CAN, RS485, GPIO, MI (R51.1)
BOOT_MODE0: 02 SOM Connectors (P1.75), 06 CAN, RS485, GPIO, MI (P5.1)
BOOT_MODE1: 02 SOM Connectors (P1.80), 06 CAN, RS485, GPIO, MI (P5.3)
BOOT_MODE2: 02 SOM Connectors (P1.82), 06 CAN, RS485, GPIO, MI (P5.5)
BOOT_MODE3: 02 SOM Connectors (P1.58), 06 CAN, RS485, GPIO, MI (P5.7)
CSI1_B_FLASH_OUT: 06 CAN, RS485, GPIO, MI (R66.1), 09 MIPI-CSI Camera Conn (U8.1)
CSI1_B_RST: 06 CAN, RS485, GPIO, MI (R65.1), 09 MIPI-CSI Camera Conn (R116.2)
CSI1_B_TRG: 06 CAN, RS485, GPIO, MI (R67.1), 09 MIPI-CSI Camera Conn (R102.1 U8.8)
CSI1_PWR_DWN_B: 06 CAN, RS485, GPIO, MI (R64.1), 09 MIPI-CSI Camera Conn (R115.2)
CSI_CLK_N: 02 SOM Connectors (P2.30), 09 MIPI-CSI Camera Conn (U7.5)
CSI_CLK_P: 02 SOM Connectors (P2.32), 09 MIPI-CSI Camera Conn (U7.4)
CSI_D0_N: 02 SOM Connectors (P2.31), 09 MIPI-CSI Camera Conn (U7.8)
CSI_D0_P: 02 SOM Connectors (P2.33), 09 MIPI-CSI Camera Conn (U7.7)
CSI_D1_N: 02 SOM Connectors (P2.35), 09 MIPI-CSI Camera Conn (U7.10)
CSI_D1_P: 02 SOM Connectors (P2.37), 09 MIPI-CSI Camera Conn (U7.9)
DSI_CLK_N: 02 SOM Connectors (P2.21), 07 MIPI-DSI LCD (L14.3)
DSI_CLK_P: 02 SOM Connectors (P2.23), 07 MIPI-DSI LCD (L14.4)
DSI_D0_N: 02 SOM Connectors (P2.1), 07 MIPI-DSI LCD (L12.3)
DSI_D0_P: 02 SOM Connectors (P2.3), 07 MIPI-DSI LCD (L12.4)
DSI_D1_N: 02 SOM Connectors (P2.15), 07 MIPI-DSI LCD (L13.3)
DSI_D1_P: 02 SOM Connectors (P2.17), 07 MIPI-DSI LCD (L13.4)
DSI_D2_N: 02 SOM Connectors (P2.5), 07 MIPI-DSI LCD (L16.3)
DSI_D2_P: 02 SOM Connectors (P2.7), 07 MIPI-DSI LCD (L16.4)
DSI_D3_N: 02 SOM Connectors (P2.11), 07 MIPI-DSI LCD (L17.3)
DSI_D3_P: 02 SOM Connectors (P2.13), 07 MIPI-DSI LCD (L17.4)
DSI_DISP_RESET: 06 CAN, RS485, GPIO, MI (R57.1), 07 MIPI-DSI LCD (P11.26 R130.1)
DSI_TOUCH_RESET: 06 CAN, RS485, GPIO, MI (R58.1), 07 MIPI-DSI LCD (P12.7 U12.1)
ECSPI3_MISO/UART7_RX: 02 SOM Connectors (P1.41), 06 CAN, RS485, GPIO, MI (U25.1)
ECSPI3_MOSI: 02 SOM Connectors (P1.35), 06 CAN, RS485, GPIO, MI (P3.14)
ECSPI3_SCLK: 02 SOM Connectors (P1.37), 06 CAN, RS485, GPIO, MI (P3.16)
ECSPI3_SS0/UART7_TX: 02 SOM Connectors (P1.39), 06 CAN, RS485, GPIO, MI (U25.4)
ECSPI4_MISO/GPIO2_19: 02 SOM Connectors (P1.59), 07 MIPI-DSI LCD (R128.1)
ECSPI4_MOSI/GPIO2_20: 02 SOM Connectors (P1.61), 08 LVDS LCD (P8.6 U6.4)
ECSPI4_SCLK/GPIO2_21: 02 SOM Connectors (P1.63), 07 MIPI-DSI LCD (R132.1)
ECSPI4_SS0: 02 SOM Connectors (P1.89), 06 CAN, RS485, GPIO, MI (P3.17)
ENET2_MDC: 02 SOM Connectors (P2.68), 03 Ethernet and Expansi (P14.11)
ENET2_MDIO: 02 SOM Connectors (P2.70), 03 Ethernet and Expansi (P14.13)
ENET2_RD0: 02 SOM Connectors (P2.41), 03 Ethernet and Expansi (P14.17)
ENET2_RD1: 02 SOM Connectors (P2.43), 03 Ethernet and Expansi (P14.19)
ENET2_RD2: 02 SOM Connectors (P2.45), 03 Ethernet and Expansi (P14.23)
ENET2_RD3: 02 SOM Connectors (P2.47), 03 Ethernet and Expansi (P14.25)
ENET2_RX_CTL: 02 SOM Connectors (P2.53), 03 Ethernet and Expansi (P14.33)
ENET2_RXC: 02 SOM Connectors (P2.55), 03 Ethernet and Expansi (P14.31)
ENET2_TD0: 02 SOM Connectors (P2.59), 03 Ethernet and Expansi (P14.20)
ENET2_TD1: 02 SOM Connectors (P2.61), 03 Ethernet and Expansi (P14.22)
ENET2_TD2: 02 SOM Connectors (P2.65), 03 Ethernet and Expansi (P14.24)
ENET2_TD3: 02 SOM Connectors (P2.63), 03 Ethernet and Expansi (P14.36)
ENET2_TX_CTL: 02 SOM Connectors (P2.67), 03 Ethernet and Expansi (P14.32)
ENET2_TXC: 02 SOM Connectors (P2.69), 03 Ethernet and Expansi (P14.30)
ETH1_LED_ACT/PHY1ADDRESS2: 02 SOM Connectors (P2.83), 03 Ethernet and Expansi (P13.P12)
ETH1_LINK-LED_10_100: 02 SOM Connectors (P2.86), 03 Ethernet and Expansi (D8.1 R193.2)
ETH1_LINK-LED_1000/INTSELECT: 02 SOM Connectors (P2.75), 03 Ethernet and Expansi (D8.2)
ETH1_MDI0N: 02 SOM Connectors (P2.73), 03 Ethernet and Expansi (P13.P2)
ETH1_MDI0P: 02 SOM Connectors (P2.74), 03 Ethernet and Expansi (P13.P1)
ETH1_MDI1N: 02 SOM Connectors (P2.80), 03 Ethernet and Expansi (P13.P4)
ETH1_MDI1P: 02 SOM Connectors (P2.78), 03 Ethernet and Expansi (P13.P3)
ETH1_MDI2N: 02 SOM Connectors (P2.81), 03 Ethernet and Expansi (P13.P8)
ETH1_MDI2P: 02 SOM Connectors (P2.79), 03 Ethernet and Expansi (P13.P7)
ETH1_MDI3N: 02 SOM Connectors (P2.85), 03 Ethernet and Expansi (P13.P10)
ETH1_MDI3P: 02 SOM Connectors (P2.84), 03 Ethernet and Expansi (P13.P9)
EXTEN_GPIO_1: 03 Ethernet and Expansi (P14.38), 06 CAN, RS485, GPIO, MI (R52.1)
EXTEN_GPIO_2: 03 Ethernet and Expansi (P14.42), 06 CAN, RS485, GPIO, MI (R53.1)
GPIO_IO00: 02 SOM Connectors (P1.28), 06 CAN, RS485, GPIO, MI (P3.3)
GPIO_IO01: 02 SOM Connectors (P1.26), 06 CAN, RS485, GPIO, MI (P3.1)
GPIO_IO02: 02 SOM Connectors (P1.30), 06 CAN, RS485, GPIO, MI (P3.5)
GPIO_IO03: 02 SOM Connectors (P1.32), 06 CAN, RS485, GPIO, MI (P3.7)
GPIO_IO04: 02 SOM Connectors (P2.58), 06 CAN, RS485, GPIO, MI (P3.20)
GPIO_IO05: 02 SOM Connectors (P2.56), 06 CAN, RS485, GPIO, MI (P3.18)
GPIO_IO07: 02 SOM Connectors (P1.98), 06 CAN, RS485, GPIO, MI (P3.6)
GPIO_IO13: 02 SOM Connectors (P1.100), 08 LVDS LCD (R88.2 U5.2)
GPIO_IO14: 02 SOM Connectors (P2.76), 06 CAN, RS485, GPIO, MI (P5.4)
GPIO_IO15: 02 SOM Connectors (P1.60), 06 CAN, RS485, GPIO, MI (P5.2)
GPIO_IO16: 02 SOM Connectors (P1.96), 06 CAN, RS485, GPIO, MI (P3.4)
GPIO_IO17: 02 SOM Connectors (P1.95), 06 CAN, RS485, GPIO, MI (P3.19)
GPIO_IO22/SPDIF_RX: 02 SOM Connectors (P1.79), 05 USB2, JTAG, SPDIF (R28.2)
GPIO_IO23/SPDIF_TX: 02 SOM Connectors (P1.81), 05 USB2, JTAG, SPDIF (C35.2)
GPIO_IO25/CAN2_TX: 02 SOM Connectors (P1.33), 06 CAN, RS485, GPIO, MI (R104.2)
GPIO_IO27/CAN2_RX: 02 SOM Connectors (P1.49), 06 CAN, RS485, GPIO, MI (R105.2)
I2C3_SCK: 02 SOM Connectors (P1.94), 06 CAN, RS485, GPIO, MI (P3.32 R79.2)
I2C3_SCL_CM: 03 Ethernet and Expansi (P14.14), 06 CAN, RS485, GPIO, MI (R76.2 R79.1 U3.19), 07 MIPI-DSI LCD (P12.4 U12.6), 08 LVDS LCD (P8.4 U6.1), 09 MIPI-CSI Camera Conn (P9.20 U9.1), 10 Console, RS232, SD,  (U23.6)
I2C3_SDA: 02 SOM Connectors (P1.91), 06 CAN, RS485, GPIO, MI (P3.34 R80.2)
I2C3_SDA_CM: 03 Ethernet and Expansi (P14.16), 06 CAN, RS485, GPIO, MI (R78.2 R80.1 U3.20), 07 MIPI-DSI LCD (P12.5 U12.4), 08 LVDS LCD (P8.5 U6.3), 09 MIPI-CSI Camera Conn (P9.21 U9.8), 10 Console, RS232, SD,  (U23.5)
JTAG_TCK: 02 SOM Connectors (P1.73), 05 USB2, JTAG, SPDIF (P4.3)
JTAG_TDI: 02 SOM Connectors (P1.71), 05 USB2, JTAG, SPDIF (P4.7)
JTAG_TDO: 02 SOM Connectors (P1.67), 05 USB2, JTAG, SPDIF (P4.5)
JTAG_TMS: 02 SOM Connectors (P1.65), 05 USB2, JTAG, SPDIF (P4.1)
LVDS_CLK_N: 02 SOM Connectors (P2.14), 08 LVDS LCD (L11.3)
LVDS_CLK_P: 02 SOM Connectors (P2.12), 08 LVDS LCD (L11.4)
LVDS_DISP_RESET: 06 CAN, RS485, GPIO, MI (R60.1), 08 LVDS LCD (C62.2 P7.36 R85.1)
LVDS_TOUCH_RESET: 06 CAN, RS485, GPIO, MI (R62.1), 08 LVDS LCD (P8.7 U6.6)
LVDS_TX0_N: 02 SOM Connectors (P2.26), 08 LVDS LCD (L7.4)
LVDS_TX0_P: 02 SOM Connectors (P2.24), 08 LVDS LCD (L7.3)
LVDS_TX1_N: 02 SOM Connectors (P2.20), 08 LVDS LCD (L6.4)
LVDS_TX1_P: 02 SOM Connectors (P2.18), 08 LVDS LCD (L6.3)
LVDS_TX2_N: 02 SOM Connectors (P2.8), 08 LVDS LCD (L9.4)
LVDS_TX2_P: 02 SOM Connectors (P2.6), 08 LVDS LCD (L9.3)
LVDS_TX3_N: 02 SOM Connectors (P2.4), 08 LVDS LCD (L10.4)
LVDS_TX3_P: 02 SOM Connectors (P2.2), 08 LVDS LCD (L10.3)
MODEM_RST: 06 CAN, RS485, GPIO, MI (R70.1), 10 Console, RS232, SD,  (P18.17)
mux_PCIe_USB_DN: 05 USB2, JTAG, SPDIF (U30.7), 10 Console, RS232, SD,  (L22.1)
mux_PCIe_USB_DP: 05 USB2, JTAG, SPDIF (U30.1), 10 Console, RS232, SD,  (L22.2)
PDM_CLK/GPIO1_8: 02 SOM Connectors (P1.21), 06 CAN, RS485, GPIO, MI (P3.8 R75.1)
PDM_DATA0: 02 SOM Connectors (P1.23), 06 CAN, RS485, GPIO, MI (P3.10 R56.2)
PDM_DATA1: 02 SOM Connectors (P1.25), 06 CAN, RS485, GPIO, MI (P3.12)
PMIC_ON_REQ: 02 SOM Connectors (P1.68), 11 Power (Q5.5)
PMIC_STBY_REQ: 02 SOM Connectors (P1.66), 11 Power (Q4.5)
POR_B_3P3: 02 SOM Connectors (P2.66 R36.1), 05 USB2, JTAG, SPDIF (R49.2)
SAI1_RXD0: 02 SOM Connectors (P1.45), 03 Ethernet and Expansi (P14.7)
SAI1_TXC/CAN1_RX: 02 SOM Connectors (P1.51), 03 Ethernet and Expansi (P14.1)
SD2_CLK: 02 SOM Connectors (P2.96), 10 Console, RS232, SD,  (R181.2)
SD2_CMD: 02 SOM Connectors (P2.100), 10 Console, RS232, SD,  (R182.2)
SD2_DATA0: 02 SOM Connectors (P2.97), 10 Console, RS232, SD,  (R177.2)
SD2_DATA1: 02 SOM Connectors (P2.99), 10 Console, RS232, SD,  (R178.2)
SD2_DATA2: 02 SOM Connectors (P2.94), 10 Console, RS232, SD,  (R179.2)
SD2_DATA3: 02 SOM Connectors (P2.98), 10 Console, RS232, SD,  (R180.2)
SD2_nCD: 02 SOM Connectors (P2.92), 10 Console, RS232, SD,  (P15.P9 R183.2)
SD2_nRST: 02 SOM Connectors (P2.51), 06 CAN, RS485, GPIO, MI (P3.30)
SD3_CLK: 02 SOM Connectors (P2.36), 06 CAN, RS485, GPIO, MI (P3.21)
SD3_CMD: 02 SOM Connectors (P2.38), 06 CAN, RS485, GPIO, MI (P3.23)
SD3_DATA0: 02 SOM Connectors (P2.42), 06 CAN, RS485, GPIO, MI (P3.25)
SD3_DATA1: 02 SOM Connectors (P2.44), 06 CAN, RS485, GPIO, MI (P3.27)
SD3_DATA2: 02 SOM Connectors (P2.48), 06 CAN, RS485, GPIO, MI (P3.22)
SD3_DATA3: 02 SOM Connectors (P2.50), 06 CAN, RS485, GPIO, MI (P3.24)
SPDIF_AUDIO_IN: 05 USB2, JTAG, SPDIF (C34.1 R29.2), 06 CAN, RS485, GPIO, MI (P3.29)
SPDIF_AUDIO_OUT: 05 USB2, JTAG, SPDIF (C36.1 R27.2 R30.1), 06 CAN, RS485, GPIO, MI (P3.31)
SW_SAI1_TXD0/CAN1_TX: 02 SOM Connectors (P1.53), 03 Ethernet and Expansi (P14.5)
SW_SAI1_TXFS: 02 SOM Connectors (P1.87), 03 Ethernet and Expansi (P14.3)
SW_UART1_TXD: 02 SOM Connectors (P1.74), 10 Console, RS232, SD,  (U41.5)
SW_UART2_TXD: 02 SOM Connectors (P1.72), 10 Console, RS232, SD,  (U33.11)
SYS_RST_PMIC: 02 SOM Connectors (P1.2 R35.1), 05 USB2, JTAG, SPDIF (R48.2)
TAMPER0: 02 SOM Connectors (P2.25), 06 CAN, RS485, GPIO, MI (P3.26)
TAMPER1: 02 SOM Connectors (P2.27), 06 CAN, RS485, GPIO, MI (P3.28)
UART1_RXD: 02 SOM Connectors (P1.76), 10 Console, RS232, SD,  (U41.4)
UART2_RXD: 02 SOM Connectors (P1.19), 10 Console, RS232, SD,  (R192.1)
USB1_DN: 02 SOM Connectors (P1.14), 04 USB1 (U27.5)
USB1_DP: 02 SOM Connectors (P1.12), 04 USB1 (U27.3)
USB1_ID: 02 SOM Connectors (P1.22), 04 USB1 (R211.2)
USB1_VBUS_3V3: 02 SOM Connectors (P1.24), 04 USB1 (R201.2 R204.2)
USB2_DN: 02 SOM Connectors (P1.5), 05 USB2, JTAG, SPDIF (U30.5)
USB2_DP: 02 SOM Connectors (P1.3), 05 USB2, JTAG, SPDIF (U30.3)
USB2_ID: 02 SOM Connectors (P1.7), 05 USB2, JTAG, SPDIF (R217.1)
USB2_VBUS_3V3: 02 SOM Connectors (P1.1), 05 USB2, JTAG, SPDIF (R220.2)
